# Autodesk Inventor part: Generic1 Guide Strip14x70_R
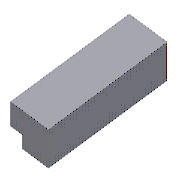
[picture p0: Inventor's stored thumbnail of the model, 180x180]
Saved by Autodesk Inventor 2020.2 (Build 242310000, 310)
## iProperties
Manager: www.cadconsulting.pl
Company: Fabian Stasiak CAD Consulting
IsCustomPart: 1
Created: 2014-02
Part Number: Generic1 Guide Strip14x70_R
Material: DIN 1.2842
Description: Tor prowadnicy
Document SubType Name: Modeling
Designer: F.Stasiak
Standard Revision: 1
Manufacturer: Generic
Language: pl-PL
Size Designation: 14x70_R
Categories: <MemberInstance><Categories><Category DisplayName="Forma wtryskowa" InternalName="349578f2-f4d4-4954-8c09-8e99297a61c0" Mnemonic="MOLD"><Category DisplayName="K
Density: 7.66 g/cm^3
Appearance: Aluminum (Machined)
Catalog Web Link: www.expertbooks.pl
Position: L
Part Type: 2
Author: F.Stasiak
Subject: Zbiór ćwiczeń. Autodesk Inventor 2020. Kurs Professional
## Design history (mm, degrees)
sketch "Sketch1"
  geometry: L1 (0, -6)-(0, 8) reference; L2 (-17.5, 6)-(-31.5, 6); L3 (-31.5, 6)-(-31.5, -4); L4 (-31.5, -4)-(-22.5, -4); L5 (-22.5, -4)-(-22.5, 0); L6 (-22.5, 0)-(-17.5, 0); L7 (-17.5, 0)-(-17.5, 6); 1 further point
  constraints: 12 end point, 3 horizontal, 3 vertical, 1 horizontal alignment
  dimensions: "d235" = 14 distance of L2.start L2.end (derived); "d236" = 10 distance of L2.end L3.end (derived); "d237" = 5 distance of L5.end L6.end (derived); "d238" = 4 distance of L4.end L5.end (derived); "d239" = 17.5 distance between parallel lines of L7 L1 (derived)
extrude "Wyciągnięcie proste_L" new body sketch "Sketch1" distance "d27" = 70 (= GS_l1); taper "d28" = 0 deg
workplane "Work Plane1"
feature "Powierzchnia zszycia1" dims "d272" = 0.254 (derived)
sketch "Sketch4"
  geometry: L1 (17.5, 0)-(17.5, 6); L2 (17.5, 6)-(31.5, 6); L3 (31.5, 6)-(31.5, -4); L4 (31.5, -4)-(22.5, -4); L5 (22.5, -4)-(22.5, 0); L6 (17.5, 0)-(22.5, 0); L7 (0, 8)-(0, -6) reference; 1 further point
  constraints: 12 end point, 3 parallel, 1 horizontal, 1 horizontal alignment, 1 perpendicular, 1 vertical
  dimensions: "d101" = 10 distance between parallel lines of L4 L2 (= GS_h2); "d240" = 14 distance of L1.end L2.end (derived); "d241" = 4 distance of L4.end L5.end (derived); "d242" = 5 distance of L1.start L5.end (derived); "d243" = 17.5 distance between parallel lines of L1 L7 (derived)
extrude "Wyciągnięcie proste_R" new body sketch "Sketch4" distance "d107" = 70 (derived); taper "d108" = 0 deg
workplane "Work Plane2"
feature "Powierzchnia zszycia2" dims "d273" = 0.254 (derived)
body "Solid1"
sketch "Sketch2"
  geometry: L1 (0, 14)-(0, 0); L2 (170, 14)-(170, 0); L3 (70, 0)-(70, 14) reference; L4 (0, 14)-(70, 14) reference; L5 (0, 0)-(70, 0) reference; L6 (0, 14)-(170, 14); L7 (0, 0)-(170, 0); 3 further points
  constraints: 8 end point, 3 point on line, 2 horizontal, 2 midpoint, 2 vertical
  dimensions: "d255" = 100 distance between parallel lines of L3 L2 (derived)
body "Srf1"
body "Srf2"
body "Srf3"
body "Srf4"
sketch "Sketch5"
  geometry: L1 (0, 14)-(170, 14); L2 (170, 14)-(170, 0); L3 (170, 0)-(0, 0); L4 (0, 0)-(0, 14); L5 (0, 14)-(70, 14) reference; L6 (70, 0)-(70, 14) reference; L7 (0, 0)-(70, 0) reference; 2 further points
  constraints: 8 end point, 6 point on line, 2 parallel, 1 collinear, 1 horizontal, 1 midpoint, 1 perpendicular
  dimensions: "d136" = 100 distance between parallel lines of L2 L6 (derived)
body "Srf5"
body "Srf6"
body "Srf7"
body "Srf8"
feature "WyciągnięcieProstePow1" dims "d81" = 10.5 (derived), "d82" = 0
feature "Zamknięcie obwiedni1" dims "d84" = 0, "d256" = 0, "d257" = 0, "d258" = 0, "d259" = 0
feature "Zamknięcie obwiedni2" dims "d86" = 0, "d260" = 0, "d261" = 0, "d262" = 0, "d263" = 0
feature "WyciągnięcieProstePow3" dims "d138" = 10.5 (derived), "d139" = 0
feature "Zamknięcie obwiedni5" dims "d250" = 0, "d264" = 0, "d265" = 0, "d266" = 0, "d267" = 0
feature "Zamknięcie obwiedni6" dims "d252" = 0, "d268" = 0, "d269" = 0, "d270" = 0, "d271" = 0
other parameters: "GS_b" = 14 [user parameter], "GS_l1" = 70 [user parameter; used in 1 equation term], "GS_h2" = 10 [user parameter; used in 1 equation term], "GS_t1" = 5 [user parameter], "GS_h3" = 4 [user parameter], "GS_es1" = 0.5 [user parameter; used in 1 equation term], "GS_esr" = 2.5 [user parameter], "GS_esw" = 5 [user parameter], "GS_esl1" = 0 [user parameter], "d96" = 0.5 (= GS_es1), "d134" = 0.5 (derived), "SL_b1" = 35 [user parameter]
